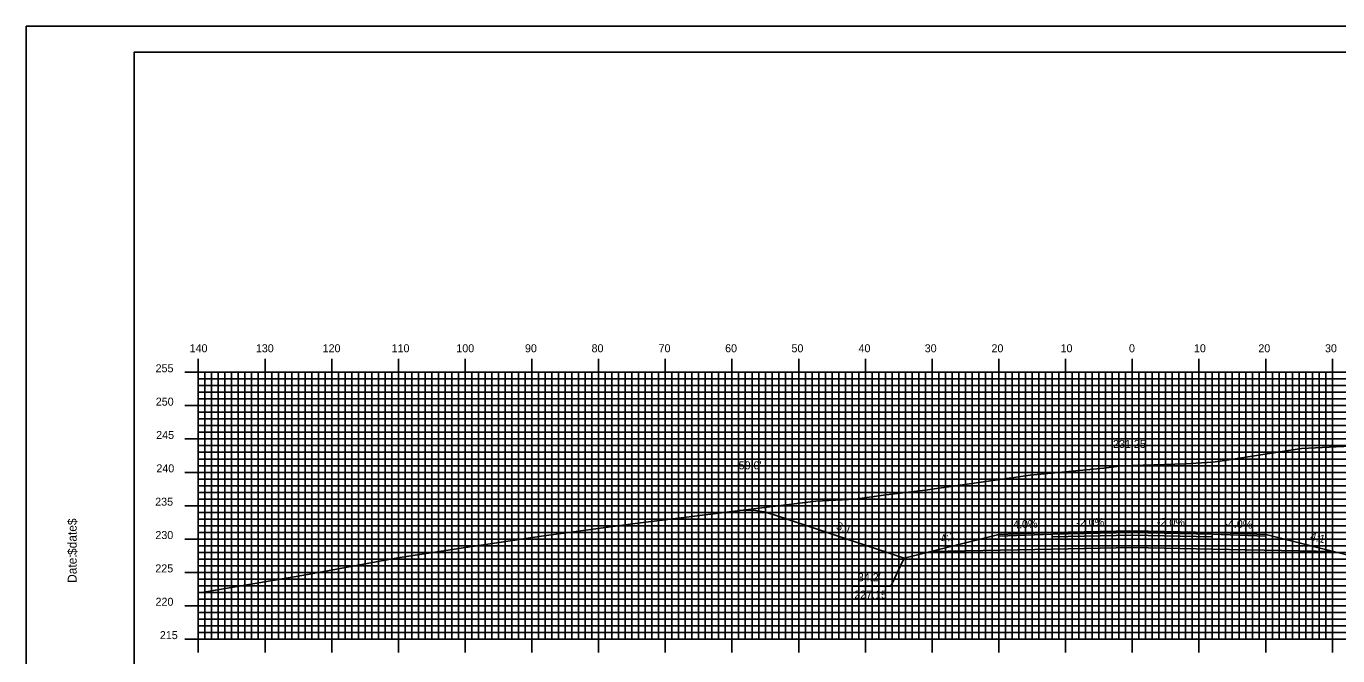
# Model space of a CAD drawing. Extents: x 1818063 to 1818407, y 442591 to 442811.
# Drawn here: x 1818063.3 to 1818259.9, y 442716.2 to 442810.5 of the extents above; entities that cross this region are included whole.
import ezdxf

# ---------------------------------------------------------------- set-up
doc = ezdxf.new("R2010")
doc.units = 0
for name, color, linetype in [('ANNOTATION', 7, 'Continuous'), ('BORDER', 7, 'Continuous'), ('D_Roadway_Centerline', 7, 'Continuous'), ('D_Roadway_Centerline_Text', 7, 'Continuous'), ('D_Roadway_Edge_Shoulder', 7, 'Continuous'), ('D_Roadway_Edge_TW', 7, 'Continuous'), ('D_Roadway_Pavement', 7, 'Continuous'), ('D_Roadway_SlopeLines', 7, 'Continuous'), ('D_Roadway_SubGrade', 7, 'Continuous'), ('D_Text_Standard', 7, 'Continuous'), ('H_V ANNOTATION', 7, 'Continuous'), ('MAJOR', 7, 'Continuous'), ('MINOR', 7, 'Continuous'), ('PLOT BOUNDARY', 7, 'Continuous'), ('S_Roadway_Centerline', 7, 'Continuous')]:
    doc.layers.add(name, color=color, linetype=linetype)

msp = doc.modelspace()

# ---------------------------------------------------------------- linework, layer by layer
at = {"layer": 'ANNOTATION'}
msp.add_lwpolyline([(1818187.27, 442726.62), (1818192.96, 442726.62), (1818194.95, 442730.81)], dxfattribs=at)
at = {"layer": 'BORDER'}
msp.add_lwpolyline([(1818079.53, 442596.67), (1818399.53, 442596.67), (1818399.53, 442806.67), (1818079.53, 442806.67)], close=True, dxfattribs=at)
at = {"layer": 'D_Roadway_Centerline'}
msp.add_lwpolyline([(1818170.17, 442737.93), (1818171.42, 442738.01), (1818172.67, 442737.95), (1818173.92, 442737.75), (1818175.17, 442737.4), (1818194.95, 442730.81), (1818198.95, 442731.81), (1818209.13, 442734.35), (1818217.13, 442734.67), (1818229.13, 442734.91), (1818241.13, 442734.67), (1818249.13, 442734.35), (1818259.3, 442731.81), (1818263.3, 442730.81), (1818319.81, 442749.65), (1818321.06, 442750.02), (1818322.31, 442750.3), (1818323.56, 442750.48), (1818324.81, 442750.58)], dxfattribs=at)
at = {"layer": 'D_Roadway_Edge_Shoulder'}
for points in [[(1818217.13, 442734.67), (1818209.13, 442734.35), (1818209.13, 442734.1), (1818217.13, 442734.42)], [(1818241.13, 442734.67), (1818249.13, 442734.35), (1818249.13, 442734.1), (1818241.13, 442734.42)]]:
    msp.add_lwpolyline(points, close=True, dxfattribs=at)
at = {"layer": 'D_Roadway_Edge_TW'}
msp.add_lwpolyline([(1818217.13, 442734.42), (1818217.13, 442734.67), (1818229.13, 442734.91), (1818241.13, 442734.67), (1818241.13, 442734.42), (1818229.13, 442734.66)], close=True, dxfattribs=at)
at = {"layer": 'D_Roadway_Pavement'}
msp.add_lwpolyline([(1818217.13, 442734.01), (1818217.13, 442734.42), (1818229.13, 442734.66), (1818241.13, 442734.42), (1818241.13, 442734.01), (1818229.13, 442734.25)], close=True, dxfattribs=at)
at = {"layer": 'D_Roadway_SlopeLines'}
for points in [[(1818194.95, 442730.81), (1818175.17, 442737.4), (1818173.92, 442737.75), (1818172.67, 442737.95), (1818171.42, 442738.01), (1818170.17, 442737.93)], [(1818209.13, 442734.35), (1818194.95, 442730.81)], [(1818249.13, 442734.35), (1818263.3, 442730.81)]]:
    msp.add_lwpolyline(points, dxfattribs=at)
at = {"layer": 'D_Roadway_SubGrade'}
msp.add_lwpolyline([(1818217.13, 442732.17), (1818198.95, 442731.81), (1818209.13, 442734.35), (1818209.13, 442734.1), (1818217.13, 442734.42), (1818229.13, 442734.66), (1818241.13, 442734.42), (1818249.13, 442734.1), (1818249.13, 442734.35), (1818259.3, 442731.81), (1818241.13, 442732.17), (1818229.13, 442732.41)], close=True, dxfattribs=at)
at = {"layer": 'MAJOR'}
for p, q in [((1818089.13, 442760.67), (1818089.13, 442758.67)), ((1818099.13, 442760.67), (1818099.13, 442758.67)), ((1818109.13, 442760.67), (1818109.13, 442758.67)), ((1818119.13, 442760.67), (1818119.13, 442758.67)), ((1818129.13, 442760.67), (1818129.13, 442758.67)), ((1818139.13, 442760.67), (1818139.13, 442758.67)), ((1818149.13, 442760.67), (1818149.13, 442758.67)), ((1818159.13, 442760.67), (1818159.13, 442758.67)), ((1818169.13, 442760.67), (1818169.13, 442758.67)), ((1818179.13, 442760.67), (1818179.13, 442758.67)), ((1818189.13, 442760.67), (1818189.13, 442758.67)), ((1818199.13, 442760.67), (1818199.13, 442758.67)), ((1818209.13, 442760.67), (1818209.13, 442758.67)), ((1818219.13, 442760.67), (1818219.13, 442758.67)), ((1818229.13, 442760.67), (1818229.13, 442758.67)), ((1818239.13, 442760.67), (1818239.13, 442758.67)), ((1818249.13, 442760.67), (1818249.13, 442758.67)), ((1818259.13, 442760.67), (1818259.13, 442758.67)), ((1818087.12, 442758.67), (1818089.13, 442758.67)), ((1818089.13, 442758.67), (1818369.13, 442758.67)), ((1818089.13, 442718.67), (1818089.13, 442758.67)), ((1818089.13, 442718.67), (1818089.13, 442758.67)), ((1818089.13, 442758.67), (1818369.13, 442758.67)), ((1818099.13, 442718.67), (1818099.13, 442758.67)), ((1818109.13, 442718.67), (1818109.13, 442758.67)), ((1818119.13, 442718.67), (1818119.13, 442758.67)), ((1818129.13, 442718.67), (1818129.13, 442758.67)), ((1818139.13, 442718.67), (1818139.13, 442758.67)), ((1818149.13, 442718.67), (1818149.13, 442758.67)), ((1818159.13, 442718.67), (1818159.13, 442758.67)), ((1818169.13, 442718.67), (1818169.13, 442758.67)), ((1818179.13, 442718.67), (1818179.13, 442758.67)), ((1818189.13, 442718.67), (1818189.13, 442758.67)), ((1818199.13, 442718.67), (1818199.13, 442758.67)), ((1818209.13, 442718.67), (1818209.13, 442758.67)), ((1818219.13, 442718.67), (1818219.13, 442758.67)), ((1818229.13, 442718.67), (1818229.13, 442758.67)), ((1818239.13, 442718.67), (1818239.13, 442758.67)), ((1818249.13, 442718.67), (1818249.13, 442758.67)), ((1818259.13, 442718.67), (1818259.13, 442758.67)), ((1818087.12, 442753.67), (1818089.13, 442753.67)), ((1818089.13, 442753.67), (1818369.13, 442753.67)), ((1818087.12, 442748.67), (1818089.13, 442748.67)), ((1818089.13, 442748.67), (1818369.13, 442748.67)), ((1818087.12, 442743.67), (1818089.13, 442743.67)), ((1818089.13, 442743.67), (1818369.13, 442743.67)), ((1818087.12, 442738.67), (1818089.13, 442738.67)), ((1818089.13, 442738.67), (1818369.13, 442738.67)), ((1818087.12, 442733.67), (1818089.13, 442733.67)), ((1818089.13, 442733.67), (1818369.13, 442733.67)), ((1818087.12, 442728.67), (1818089.13, 442728.67)), ((1818089.13, 442728.67), (1818369.13, 442728.67)), ((1818087.12, 442723.67), (1818089.13, 442723.67)), ((1818089.13, 442723.67), (1818369.13, 442723.67)), ((1818087.12, 442718.67), (1818089.13, 442718.67)), ((1818089.13, 442718.67), (1818369.13, 442718.67)), ((1818089.13, 442718.67), (1818369.13, 442718.67)), ((1818089.13, 442716.66), (1818089.13, 442718.67)), ((1818099.13, 442716.66), (1818099.13, 442718.67)), ((1818109.13, 442716.66), (1818109.13, 442718.67)), ((1818119.13, 442716.66), (1818119.13, 442718.67)), ((1818129.13, 442716.66), (1818129.13, 442718.67)), ((1818139.13, 442716.66), (1818139.13, 442718.67)), ((1818149.13, 442716.66), (1818149.13, 442718.67)), ((1818159.13, 442716.66), (1818159.13, 442718.67)), ((1818169.13, 442716.66), (1818169.13, 442718.67)), ((1818179.13, 442716.66), (1818179.13, 442718.67)), ((1818189.13, 442716.66), (1818189.13, 442718.67)), ((1818199.13, 442716.66), (1818199.13, 442718.67)), ((1818209.13, 442716.66), (1818209.13, 442718.67)), ((1818219.13, 442716.66), (1818219.13, 442718.67)), ((1818229.13, 442716.66), (1818229.13, 442718.67)), ((1818239.13, 442716.66), (1818239.13, 442718.67)), ((1818249.13, 442716.66), (1818249.13, 442718.67)), ((1818259.13, 442716.66), (1818259.13, 442718.67))]:
    msp.add_line(p, q, dxfattribs=at)
at = {"layer": 'MINOR'}
for p, q in [((1818089.13, 442757.67), (1818369.13, 442757.67)), ((1818089.13, 442757.67), (1818091.13, 442757.67)), ((1818090.13, 442718.67), (1818090.13, 442758.67)), ((1818091.13, 442718.67), (1818091.13, 442758.67)), ((1818092.13, 442718.67), (1818092.13, 442758.67)), ((1818093.13, 442718.67), (1818093.13, 442758.67)), ((1818094.13, 442718.67), (1818094.13, 442758.67)), ((1818095.13, 442718.67), (1818095.13, 442758.67)), ((1818096.13, 442718.67), (1818096.13, 442758.67)), ((1818097.13, 442718.67), (1818097.13, 442758.67)), ((1818098.13, 442718.67), (1818098.13, 442758.67)), ((1818100.13, 442718.67), (1818100.13, 442758.67)), ((1818101.13, 442718.67), (1818101.13, 442758.67)), ((1818102.13, 442718.67), (1818102.13, 442758.67)), ((1818103.13, 442718.67), (1818103.13, 442758.67)), ((1818104.13, 442718.67), (1818104.13, 442758.67)), ((1818105.13, 442718.67), (1818105.13, 442758.67)), ((1818106.13, 442718.67), (1818106.13, 442758.67)), ((1818107.13, 442718.67), (1818107.13, 442758.67)), ((1818108.13, 442718.67), (1818108.13, 442758.67)), ((1818110.13, 442718.67), (1818110.13, 442758.67)), ((1818111.13, 442718.67), (1818111.13, 442758.67)), ((1818112.13, 442718.67), (1818112.13, 442758.67)), ((1818113.13, 442718.67), (1818113.13, 442758.67)), ((1818114.13, 442718.67), (1818114.13, 442758.67)), ((1818115.13, 442718.67), (1818115.13, 442758.67)), ((1818116.13, 442718.67), (1818116.13, 442758.67)), ((1818117.13, 442718.67), (1818117.13, 442758.67)), ((1818118.13, 442718.67), (1818118.13, 442758.67)), ((1818120.13, 442718.67), (1818120.13, 442758.67)), ((1818121.13, 442718.67), (1818121.13, 442758.67)), ((1818122.13, 442718.67), (1818122.13, 442758.67)), ((1818123.13, 442718.67), (1818123.13, 442758.67)), ((1818124.13, 442718.67), (1818124.13, 442758.67)), ((1818125.13, 442718.67), (1818125.13, 442758.67)), ((1818126.13, 442718.67), (1818126.13, 442758.67)), ((1818127.13, 442718.67), (1818127.13, 442758.67)), ((1818128.13, 442718.67), (1818128.13, 442758.67)), ((1818130.13, 442718.67), (1818130.13, 442758.67)), ((1818131.13, 442718.67), (1818131.13, 442758.67)), ((1818132.13, 442718.67), (1818132.13, 442758.67)), ((1818133.13, 442718.67), (1818133.13, 442758.67)), ((1818134.13, 442718.67), (1818134.13, 442758.67)), ((1818135.13, 442718.67), (1818135.13, 442758.67)), ((1818136.13, 442718.67), (1818136.13, 442758.67)), ((1818137.13, 442718.67), (1818137.13, 442758.67)), ((1818138.13, 442718.67), (1818138.13, 442758.67)), ((1818140.13, 442718.67), (1818140.13, 442758.67)), ((1818141.13, 442718.67), (1818141.13, 442758.67)), ((1818142.13, 442718.67), (1818142.13, 442758.67)), ((1818143.13, 442718.67), (1818143.13, 442758.67)), ((1818144.13, 442718.67), (1818144.13, 442758.67)), ((1818145.13, 442718.67), (1818145.13, 442758.67)), ((1818146.13, 442718.67), (1818146.13, 442758.67)), ((1818147.13, 442718.67), (1818147.13, 442758.67)), ((1818148.13, 442718.67), (1818148.13, 442758.67)), ((1818150.13, 442718.67), (1818150.13, 442758.67)), ((1818151.13, 442718.67), (1818151.13, 442758.67)), ((1818152.13, 442718.67), (1818152.13, 442758.67)), ((1818153.13, 442718.67), (1818153.13, 442758.67)), ((1818154.13, 442718.67), (1818154.13, 442758.67)), ((1818155.13, 442718.67), (1818155.13, 442758.67)), ((1818156.13, 442718.67), (1818156.13, 442758.67)), ((1818157.13, 442718.67), (1818157.13, 442758.67)), ((1818158.13, 442718.67), (1818158.13, 442758.67)), ((1818160.13, 442718.67), (1818160.13, 442758.67)), ((1818161.13, 442718.67), (1818161.13, 442758.67)), ((1818162.13, 442718.67), (1818162.13, 442758.67)), ((1818163.13, 442718.67), (1818163.13, 442758.67)), ((1818164.13, 442718.67), (1818164.13, 442758.67)), ((1818165.13, 442718.67), (1818165.13, 442758.67)), ((1818166.13, 442718.67), (1818166.13, 442758.67)), ((1818167.13, 442718.67), (1818167.13, 442758.67)), ((1818168.13, 442718.67), (1818168.13, 442758.67)), ((1818170.13, 442718.67), (1818170.13, 442758.67)), ((1818171.13, 442718.67), (1818171.13, 442758.67)), ((1818172.13, 442718.67), (1818172.13, 442758.67)), ((1818173.13, 442718.67), (1818173.13, 442758.67)), ((1818174.13, 442718.67), (1818174.13, 442758.67)), ((1818175.13, 442718.67), (1818175.13, 442758.67)), ((1818176.13, 442718.67), (1818176.13, 442758.67)), ((1818177.13, 442718.67), (1818177.13, 442758.67)), ((1818178.13, 442718.67), (1818178.13, 442758.67)), ((1818180.13, 442718.67), (1818180.13, 442758.67)), ((1818181.13, 442718.67), (1818181.13, 442758.67)), ((1818182.13, 442718.67), (1818182.13, 442758.67)), ((1818183.13, 442718.67), (1818183.13, 442758.67)), ((1818184.13, 442718.67), (1818184.13, 442758.67)), ((1818185.13, 442718.67), (1818185.13, 442758.67)), ((1818186.13, 442718.67), (1818186.13, 442758.67)), ((1818187.13, 442718.67), (1818187.13, 442758.67)), ((1818188.13, 442718.67), (1818188.13, 442758.67)), ((1818190.13, 442718.67), (1818190.13, 442758.67)), ((1818191.13, 442718.67), (1818191.13, 442758.67)), ((1818192.13, 442718.67), (1818192.13, 442758.67)), ((1818193.13, 442718.67), (1818193.13, 442758.67)), ((1818194.13, 442718.67), (1818194.13, 442758.67)), ((1818195.13, 442718.67), (1818195.13, 442758.67)), ((1818196.13, 442718.67), (1818196.13, 442758.67)), ((1818197.13, 442718.67), (1818197.13, 442758.67)), ((1818198.13, 442718.67), (1818198.13, 442758.67)), ((1818200.13, 442718.67), (1818200.13, 442758.67)), ((1818201.13, 442718.67), (1818201.13, 442758.67)), ((1818202.13, 442718.67), (1818202.13, 442758.67)), ((1818203.13, 442718.67), (1818203.13, 442758.67)), ((1818204.13, 442718.67), (1818204.13, 442758.67)), ((1818205.13, 442718.67), (1818205.13, 442758.67)), ((1818206.13, 442718.67), (1818206.13, 442758.67)), ((1818207.13, 442718.67), (1818207.13, 442758.67)), ((1818208.13, 442718.67), (1818208.13, 442758.67)), ((1818210.13, 442718.67), (1818210.13, 442758.67)), ((1818211.13, 442718.67), (1818211.13, 442758.67)), ((1818212.13, 442718.67), (1818212.13, 442758.67)), ((1818213.13, 442718.67), (1818213.13, 442758.67)), ((1818214.13, 442718.67), (1818214.13, 442758.67)), ((1818215.13, 442718.67), (1818215.13, 442758.67)), ((1818216.13, 442718.67), (1818216.13, 442758.67)), ((1818217.13, 442718.67), (1818217.13, 442758.67)), ((1818218.13, 442718.67), (1818218.13, 442758.67)), ((1818220.13, 442718.67), (1818220.13, 442758.67)), ((1818221.13, 442718.67), (1818221.13, 442758.67)), ((1818222.13, 442718.67), (1818222.13, 442758.67)), ((1818223.13, 442718.67), (1818223.13, 442758.67)), ((1818224.13, 442718.67), (1818224.13, 442758.67)), ((1818225.13, 442718.67), (1818225.13, 442758.67)), ((1818226.13, 442718.67), (1818226.13, 442758.67)), ((1818227.13, 442718.67), (1818227.13, 442758.67)), ((1818228.13, 442718.67), (1818228.13, 442758.67)), ((1818230.13, 442718.67), (1818230.13, 442758.67)), ((1818231.13, 442718.67), (1818231.13, 442758.67)), ((1818232.13, 442718.67), (1818232.13, 442758.67)), ((1818233.13, 442718.67), (1818233.13, 442758.67)), ((1818234.13, 442718.67), (1818234.13, 442758.67)), ((1818235.13, 442718.67), (1818235.13, 442758.67)), ((1818236.13, 442718.67), (1818236.13, 442758.67)), ((1818237.13, 442718.67), (1818237.13, 442758.67)), ((1818238.13, 442718.67), (1818238.13, 442758.67)), ((1818240.13, 442718.67), (1818240.13, 442758.67)), ((1818241.13, 442718.67), (1818241.13, 442758.67)), ((1818242.13, 442718.67), (1818242.13, 442758.67)), ((1818243.13, 442718.67), (1818243.13, 442758.67)), ((1818244.13, 442718.67), (1818244.13, 442758.67)), ((1818245.13, 442718.67), (1818245.13, 442758.67)), ((1818246.13, 442718.67), (1818246.13, 442758.67)), ((1818247.13, 442718.67), (1818247.13, 442758.67)), ((1818248.13, 442718.67), (1818248.13, 442758.67)), ((1818250.13, 442718.67), (1818250.13, 442758.67)), ((1818251.13, 442718.67), (1818251.13, 442758.67)), ((1818252.13, 442718.67), (1818252.13, 442758.67)), ((1818253.13, 442718.67), (1818253.13, 442758.67)), ((1818254.13, 442718.67), (1818254.13, 442758.67)), ((1818255.13, 442718.67), (1818255.13, 442758.67)), ((1818256.13, 442718.67), (1818256.13, 442758.67)), ((1818257.13, 442718.67), (1818257.13, 442758.67)), ((1818258.13, 442718.67), (1818258.13, 442758.67)), ((1818089.13, 442756.67), (1818369.13, 442756.67)), ((1818089.13, 442756.67), (1818091.13, 442756.67)), ((1818089.13, 442755.67), (1818369.13, 442755.67)), ((1818089.13, 442755.67), (1818091.13, 442755.67)), ((1818089.13, 442754.67), (1818369.13, 442754.67)), ((1818089.13, 442754.67), (1818091.13, 442754.67)), ((1818089.13, 442752.67), (1818369.13, 442752.67)), ((1818089.13, 442752.67), (1818091.13, 442752.67)), ((1818089.13, 442751.67), (1818369.13, 442751.67)), ((1818089.13, 442751.67), (1818091.13, 442751.67)), ((1818089.13, 442750.67), (1818369.13, 442750.67)), ((1818089.13, 442750.67), (1818091.13, 442750.67)), ((1818089.13, 442749.67), (1818369.13, 442749.67)), ((1818089.13, 442749.67), (1818091.13, 442749.67)), ((1818089.13, 442747.67), (1818369.13, 442747.67)), ((1818089.13, 442747.67), (1818091.13, 442747.67)), ((1818089.13, 442746.67), (1818369.13, 442746.67)), ((1818089.13, 442746.67), (1818091.13, 442746.67)), ((1818089.13, 442745.67), (1818369.13, 442745.67)), ((1818089.13, 442745.67), (1818091.13, 442745.67)), ((1818089.13, 442744.67), (1818369.13, 442744.67)), ((1818089.13, 442744.67), (1818091.13, 442744.67)), ((1818089.13, 442742.67), (1818369.13, 442742.67)), ((1818089.13, 442742.67), (1818091.13, 442742.67)), ((1818089.13, 442741.67), (1818369.13, 442741.67)), ((1818089.13, 442741.67), (1818091.13, 442741.67)), ((1818089.13, 442740.67), (1818369.13, 442740.67)), ((1818089.13, 442740.67), (1818091.13, 442740.67)), ((1818089.13, 442739.67), (1818369.13, 442739.67)), ((1818089.13, 442739.67), (1818091.13, 442739.67)), ((1818089.13, 442737.67), (1818369.13, 442737.67)), ((1818089.13, 442737.67), (1818091.13, 442737.67)), ((1818089.13, 442736.67), (1818369.13, 442736.67)), ((1818089.13, 442736.67), (1818091.13, 442736.67)), ((1818089.13, 442735.67), (1818369.13, 442735.67)), ((1818089.13, 442735.67), (1818091.13, 442735.67)), ((1818089.13, 442734.67), (1818369.13, 442734.67)), ((1818089.13, 442734.67), (1818091.13, 442734.67)), ((1818089.13, 442732.67), (1818369.13, 442732.67)), ((1818089.13, 442732.67), (1818091.13, 442732.67)), ((1818089.13, 442731.67), (1818369.13, 442731.67)), ((1818089.13, 442731.67), (1818091.13, 442731.67)), ((1818089.13, 442730.67), (1818369.13, 442730.67)), ((1818089.13, 442730.67), (1818091.13, 442730.67)), ((1818089.13, 442729.67), (1818369.13, 442729.67)), ((1818089.13, 442729.67), (1818091.13, 442729.67)), ((1818089.13, 442727.67), (1818369.13, 442727.67)), ((1818089.13, 442727.67), (1818091.13, 442727.67)), ((1818089.13, 442726.67), (1818369.13, 442726.67)), ((1818089.13, 442726.67), (1818091.13, 442726.67)), ((1818089.13, 442725.67), (1818369.13, 442725.67)), ((1818089.13, 442725.67), (1818091.13, 442725.67)), ((1818089.13, 442724.67), (1818369.13, 442724.67)), ((1818089.13, 442724.67), (1818091.13, 442724.67)), ((1818089.13, 442722.67), (1818369.13, 442722.67)), ((1818089.13, 442722.67), (1818091.13, 442722.67)), ((1818089.13, 442721.67), (1818369.13, 442721.67)), ((1818089.13, 442721.67), (1818091.13, 442721.67)), ((1818089.13, 442720.67), (1818369.13, 442720.67)), ((1818089.13, 442720.67), (1818091.13, 442720.67)), ((1818089.13, 442719.67), (1818369.13, 442719.67)), ((1818089.13, 442719.67), (1818091.13, 442719.67))]:
    msp.add_line(p, q, dxfattribs=at)
at = {"layer": 'PLOT BOUNDARY'}
msp.add_lwpolyline([(1818063.34, 442590.55), (1818403.34, 442590.55), (1818403.34, 442810.55), (1818063.34, 442810.55)], close=True, dxfattribs=at)
at = {"layer": 'S_Roadway_Centerline'}
msp.add_lwpolyline([(1818089.13, 442725.61), (1818089.68, 442725.67), (1818105.23, 442728.3), (1818119.04, 442730.87), (1818129.2, 442732.41), (1818140.58, 442734.11), (1818154.61, 442736.01), (1818181.68, 442739.35), (1818187.58, 442739.66), (1818191.86, 442740.26), (1818198.08, 442741.01), (1818213.82, 442743.27), (1818224.88, 442744.3), (1818227.61, 442744.64), (1818237.12, 442744.97), (1818241.14, 442745.22), (1818242.29, 442745.34), (1818254.52, 442747.23), (1818259.69, 442747.49), (1818267.78, 442747.82)], dxfattribs=at)

# ---------------------------------------------------------------- texts
at = {"layer": 'ANNOTATION'}
for s, rotation, p in [('3:1', 341.5652, (1818184.66, 442735.15)), ('-4.0%', 2.2906, (1818210.76, 442735.22)), ('-2.0%', 1.1458, (1818220.73, 442735.55)), ('-2.0%', 358.8542, (1818232.81, 442735.64)), ('-4.0%', 357.7094, (1818242.92, 442735.4)), ('4:1', 14.0362, (1818200.57, 442733.08)), ('4:1', 345.9638, (1818255.72, 442733.57))]:
    msp.add_text(s, height=1.2, rotation=rotation, dxfattribs=at).set_placement(p)
for s, p in [("34.2'", (1818188, 442727.34)), ('227.15', (1818187.45, 442724.74))]:
    msp.add_text(s, height=1.2, dxfattribs=at).set_placement(p)
at = {"layer": 'BORDER'}
for s, p in [('$date$', (1818070.9, 442731.28)), ('Date:', (1818070.9, 442727.1))]:
    msp.add_text(s, height=1.339, rotation=90, dxfattribs=at).set_placement(p)
at = {"layer": 'D_Roadway_Centerline'}
for s, p in [('C', (1818229.12, 442734.91)), ('L', (1818229.13, 442734.91))]:
    msp.add_text(s, height=0.0146, dxfattribs=at).set_placement(p)
at = {"layer": 'D_Roadway_Centerline_Text'}
msp.add_text('231.25', height=1.2, dxfattribs=at).set_placement((1818226.25, 442747.33))
at = {"layer": 'D_Text_Standard'}
msp.add_text("59.0'", height=1.2, dxfattribs=at).set_placement((1818170.14, 442744.12))
at = {"layer": 'H_V ANNOTATION'}
for s, p in [('140', (1818087.83, 442761.67)), ('130', (1818097.76, 442761.67)), ('120', (1818107.77, 442761.67)), ('110', (1818118.11, 442761.67)), ('100', (1818127.81, 442761.67)), ('90', (1818138.1, 442761.67)), ('80', (1818148.08, 442761.67)), ('70', (1818158.13, 442761.67)), ('60', (1818168.1, 442761.67)), ('50', (1818178.05, 442761.67)), ('40', (1818188.1, 442761.67)), ('30', (1818198.02, 442761.67)), ('20', (1818208.03, 442761.67)), ('10', (1818218.38, 442761.67)), ('0', (1818228.64, 442761.67)), ('10', (1818238.38, 442761.67)), ('20', (1818248.03, 442761.67)), ('30', (1818258.02, 442761.67)), ('255', (1818082.73, 442758.67)), ('250', (1818082.76, 442753.67)), ('245', (1818082.82, 442748.67)), ('240', (1818082.85, 442743.67)), ('235', (1818082.67, 442738.67)), ('230', (1818082.7, 442733.67)), ('225', (1818082.69, 442728.67)), ('220', (1818082.72, 442723.67)), ('215', (1818083.37, 442718.67))]:
    msp.add_text(s, height=1.2, dxfattribs=at).set_placement(p)
at = {"layer": 'MAJOR'}
msp.add_text('-', height=0.012, dxfattribs=at).set_placement((1818089.12, 442718.67))

doc.saveas('drawing.dxf')
